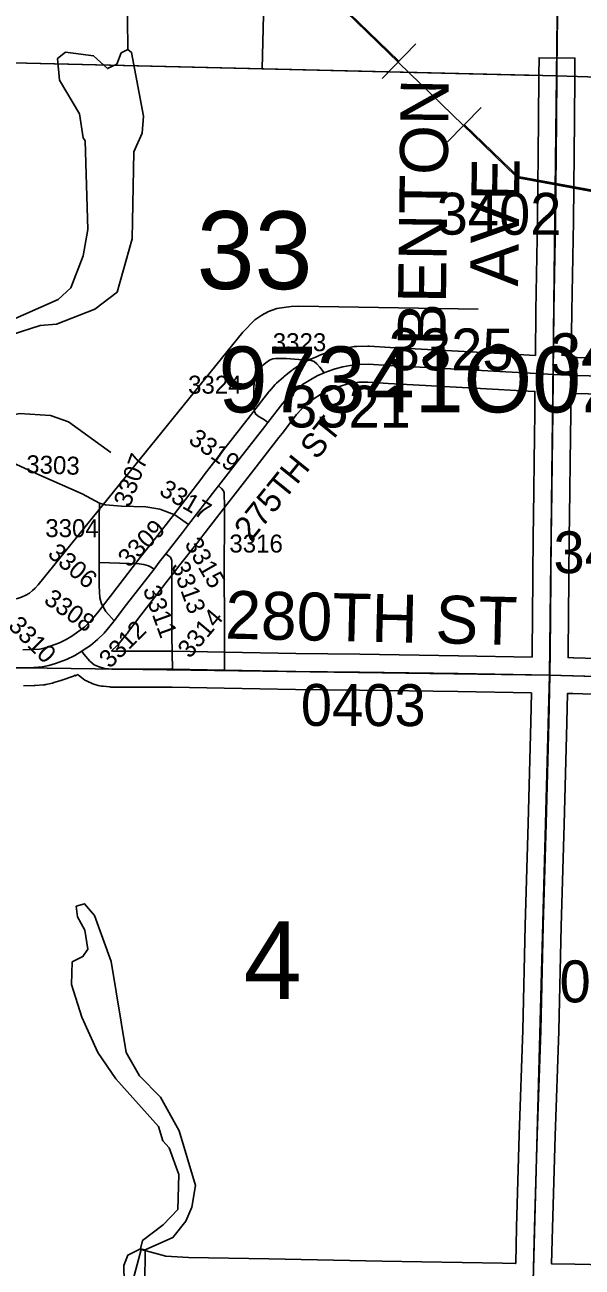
# Model space of a CAD drawing. Extents: x -157.2 to -99.3, y 12.2 to 46.2.
# Drawn here: x -144.748 to -143.818, y 22.152 to 24.227 of the extents above; entities that cross this region are included whole.
import ezdxf

# ---------------------------------------------------------------- set-up
doc = ezdxf.new("R2010")
doc.units = 0
for name, color, linetype in [('tdCoCityStreetMinor', 7, 'Continuous'), ('tdCoCorpBndry', 7, 'Continuous'), ('tdCoDirctArrow', 7, 'Continuous'), ('tdCoHydroRiver', 7, 'Continuous'), ('tdCoPipe', 7, 'Continuous'), ('tdCoSecRdNmbr', 7, 'Continuous'), ('tdCoSecRdTxt', 7, 'Continuous'), ('tdCoSecRteBand', 7, 'Continuous'), ('tdCoSecRteCL', 7, 'Continuous'), ('tdCoSectLine', 7, 'Continuous'), ('tdCoSectLinePart', 7, 'Continuous'), ('tdCoSectNmbr', 7, 'Continuous'), ('tdCoStrucPriMaintName', 7, 'Continuous'), ('tdCoSurfAsphaltUnbanded', 7, 'Continuous'), ('tdCoSurfConc', 7, 'Continuous'), ('tdCoSurfConcUnbanded', 7, 'Continuous'), ('tdCoSurfGravel', 7, 'Continuous'), ('tdCoSurfGravelUnbanded', 7, 'Continuous'), ('tdCoTwpBndryShd', 7, 'Continuous')]:
    doc.layers.add(name, color=color, linetype=linetype)

msp = doc.modelspace()

# ---------------------------------------------------------------- linework, layer by layer
at = {"layer": 'tdCoCityStreetMinor'}
msp.add_lwpolyline([(-143.8604, 24.1421), (-143.8598, 24.2064), (-143.8588, 24.2562), (-143.8573, 24.3977), (-143.8563, 24.434), (-143.8558, 24.5183)], dxfattribs=at)
at = {"layer": 'tdCoCorpBndry'}
msp.add_lwpolyline([(-143.7635, 24.3875), (-143.6972, 24.1343), (-143.6054, 23.7984), (-143.6103, 23.7579), (-143.6243, 23.7211), (-143.68, 23.6375), (-143.8278, 23.6417), (-143.8666, 23.6435), (-143.8652, 23.7494), (-143.8627, 23.9001), (-143.861, 24.0683), (-143.8604, 24.1421), (-144.3519, 24.154), (-144.3395, 24.6706)], dxfattribs=at)
at = {"layer": 'tdCoDirctArrow'}
msp.add_lwpolyline([(-143.9919, 23.7526), (-144.2911, 23.7574), (-144.3037, 23.757), (-144.3159, 23.7553), (-144.3274, 23.7536), (-144.3413, 23.7486), (-144.3527, 23.7422), (-144.3641, 23.7346), (-144.3846, 23.7142), (-144.7261, 23.2922), (-144.7306, 23.2864), (-144.7353, 23.2823), (-144.7402, 23.2783), (-144.7462, 23.2747), (-144.7537, 23.2712), (-144.7601, 23.2691), (-144.7684, 23.2674), (-144.7835, 23.2674), (-145.0438, 23.274)], dxfattribs=at)
at = {"layer": 'tdCoHydroRiver'}
for points in [[(-145.0194, 24.7742), (-144.9128, 24.7502), (-144.8286, 24.7205), (-144.6998, 24.6515), (-144.6677, 24.6189), (-144.6375, 24.5784), (-144.6293, 24.5386), (-144.6196, 24.4988), (-144.6146, 24.4592), (-144.6072, 24.4447), (-144.5973, 24.3591), (-144.5858, 24.3255), (-144.5849, 24.3066), (-144.5776, 24.2889), (-144.5762, 24.1862)], [(-145.0435, 23.7042), (-144.9954, 23.679), (-144.9227, 23.6813), (-144.875, 23.6923), (-144.8197, 23.6937), (-144.7223, 23.7252), (-144.6954, 23.7274), (-144.6315, 23.7522), (-144.5942, 23.7809), (-144.5692, 23.8701), (-144.566, 24.0153), (-144.5524, 24.0465), (-144.5499, 24.0748), (-144.57, 24.1813), (-144.5762, 24.1862)], [(-144.6475, 24.0338), (-144.6505, 24.0387), (-144.6571, 24.0784), (-144.69, 24.1347), (-144.6935, 24.1712), (-144.6805, 24.1818), (-144.6334, 24.1755), (-144.6104, 24.1542), (-144.5944, 24.1616), (-144.5874, 24.1803), (-144.5762, 24.1862)], [(-145.0435, 23.7042), (-145.0352, 23.7166), (-145.0174, 23.7302), (-144.9857, 23.7323), (-144.8443, 23.7134), (-144.779, 23.7302), (-144.6925, 23.7684), (-144.6713, 23.7882), (-144.6507, 23.8413), (-144.6429, 23.8852), (-144.6475, 24.0338)], [(-144.8558, 23.5559), (-144.7572, 23.5779), (-144.7052, 23.5746), (-144.6755, 23.5641), (-144.6046, 23.5128)], [(-144.6626, 22.7551), (-144.6601, 22.7376), (-144.6482, 22.7151), (-144.6429, 22.6833), (-144.6512, 22.671), (-144.6689, 22.6621), (-144.6701, 22.6242), (-144.6529, 22.57), (-144.6265, 22.5107), (-144.5963, 22.467), (-144.5248, 22.3872), (-144.5177, 22.3633), (-144.507, 22.3519), (-144.4911, 22.3072), (-144.493, 22.2488), (-144.5175, 22.2228), (-144.5515, 22.197), (-144.5552, 22.1829)], [(-144.6626, 22.7551), (-144.6483, 22.7593), (-144.6316, 22.7398), (-144.6041, 22.6631), (-144.5791, 22.5107), (-144.5567, 22.472), (-144.5216, 22.4361), (-144.4903, 22.3798), (-144.4633, 22.2889), (-144.4692, 22.2527), (-144.4794, 22.2294), (-144.5009, 22.2017), (-144.5473, 22.1811)], [(-144.5552, 22.1829), (-144.576, 22.1726), (-144.5829, 22.1554), (-144.5816, 22.1001), (-144.5574, 22.0661), (-144.5266, 22.0446), (-144.5134, 22.0126), (-144.5071, 22.0108)], [(-144.5552, 22.1829), (-144.5473, 22.1811)], [(-144.5473, 22.1811), (-144.5476, 22.1243), (-144.5449, 22.1115), (-144.4932, 22.0498)]]:
    msp.add_lwpolyline(points, dxfattribs=at)
at = {"layer": 'tdCoPipe'}
for p, q in [((-144.0958, 24.1953), (-144.1518, 24.1375)), ((-143.9866, 24.0894), (-144.0427, 24.0316))]:
    msp.add_line(p, q, dxfattribs=at)
for points in [[(-143.1022, 23.5122), (-143.2095, 23.8428), (-143.9285, 23.9743), (-144.6565, 24.6805), (-145.5794, 24.8267), (-145.6123, 26.3736), (-146.0293, 26.3674), (-146.0413, 27.397)], [(-144.1238, 24.1664), (-144.3399, 24.376)], [(-143.7528, 23.9399), (-143.9223, 23.9709), (-144.0147, 24.0605)]]:
    msp.add_lwpolyline(points, dxfattribs=at)
at = {"layer": 'tdCoSecRteBand'}
for points in [[(-144.7517, 23.1832), (-144.7349, 23.1837), (-144.7238, 23.1846), (-144.7156, 23.1864), (-144.7061, 23.1893), (-144.6902, 23.195), (-144.679, 23.2005), (-144.6698, 23.206), (-144.6478, 23.222), (-144.647, 23.2227), (-144.6378, 23.2317), (-144.6244, 23.248), (-144.6229, 23.25), (-144.6021, 23.2774), (-144.6021, 23.2775), (-144.602, 23.2776), (-144.5563, 23.3368), (-144.5475, 23.3482), (-144.5474, 23.3483), (-144.5473, 23.3483), (-144.5364, 23.3623), (-144.5085, 23.3979), (-144.4985, 23.4108), (-144.4546, 23.4678), (-144.4545, 23.4679), (-144.4545, 23.4679), (-144.4486, 23.4755), (-144.4137, 23.5207), (-144.4136, 23.5207), (-144.4136, 23.5207), (-144.3716, 23.5747), (-144.3663, 23.5815), (-144.3415, 23.6138), (-144.3408, 23.6146), (-144.3401, 23.6154), (-144.3304, 23.6263), (-144.3292, 23.6276), (-144.3279, 23.6288), (-144.3165, 23.639), (-144.316, 23.6394), (-144.3155, 23.6399), (-144.3036, 23.6496), (-144.3022, 23.6507), (-144.3008, 23.6516), (-144.2845, 23.6621), (-144.2833, 23.6628), (-144.282, 23.6635), (-144.273, 23.6681), (-144.272, 23.6687), (-144.2709, 23.6691), (-144.2604, 23.6735), (-144.2546, 23.6759), (-144.2537, 23.6763), (-144.2528, 23.6766), (-144.2402, 23.681), (-144.2394, 23.6813), (-144.2385, 23.6815), (-144.2256, 23.6851), (-144.2239, 23.6856), (-144.2222, 23.6859), (-144.2101, 23.6878), (-144.1986, 23.6898), (-144.1963, 23.6901), (-144.194, 23.6902), (-144.1758, 23.6904), (-144.1747, 23.6904), (-144.1737, 23.6904), (-144.1385, 23.6884), (-144.1384, 23.6884), (-144.1384, 23.6884), (-144.0968, 23.686), (-143.9945, 23.6804), (-143.8962, 23.6751), (-143.8952, 23.7498), (-143.8952, 23.7498), (-143.8952, 23.7499), (-143.8927, 23.9005), (-143.891, 24.0686), (-143.8904, 24.1424), (-143.8901, 24.1724), (-143.8301, 24.1718), (-143.8304, 24.1419), (-143.831, 24.068), (-143.831, 24.068), (-143.831, 24.068), (-143.8327, 23.8998), (-143.8327, 23.8997), (-143.8327, 23.8996), (-143.8352, 23.749), (-143.8363, 23.6721), (-143.8353, 23.6721), (-143.8266, 23.6717), (-143.6791, 23.6675)], [(-143.9016, 23.1714), (-143.9016, 23.1715), (-143.9014, 23.1829), (-143.9009, 23.2377), (-143.9009, 23.2377), (-143.9009, 23.2377), (-143.8996, 23.3731), (-143.8994, 23.4061), (-143.8994, 23.4062), (-143.8994, 23.4063), (-143.8977, 23.5409), (-143.8977, 23.5409), (-143.8977, 23.5409), (-143.8972, 23.5773), (-143.8969, 23.6139), (-143.897, 23.6139), (-143.897, 23.6149), (-143.898, 23.615), (-143.898, 23.6151), (-143.9977, 23.6205), (-143.9977, 23.6205), (-143.9977, 23.6205), (-144.1001, 23.6261), (-144.1002, 23.6261), (-144.1003, 23.6261), (-144.1418, 23.6285), (-144.176, 23.6304), (-144.1909, 23.6302), (-144.2004, 23.6286), (-144.2005, 23.6286), (-144.2006, 23.6286), (-144.211, 23.6269), (-144.2214, 23.624), (-144.2323, 23.6202), (-144.2372, 23.6182), (-144.2466, 23.6142), (-144.2533, 23.6108), (-144.267, 23.602), (-144.277, 23.5938), (-144.2867, 23.5852), (-144.2946, 23.5763), (-144.3188, 23.5449), (-144.3241, 23.538), (-144.3241, 23.5379), (-144.3242, 23.5379), (-144.3662, 23.4839), (-144.4012, 23.4388), (-144.4071, 23.4312), (-144.451, 23.3742), (-144.461, 23.3611), (-144.4611, 23.361), (-144.4612, 23.3609), (-144.4892, 23.3253), (-144.5001, 23.3114), (-144.5088, 23.3001), (-144.5544, 23.2411), (-144.575, 23.2138), (-144.5769, 23.2113), (-144.5773, 23.2108), (-144.5777, 23.2103), (-144.5925, 23.1923), (-144.5936, 23.191), (-144.5947, 23.1899), (-144.6033, 23.1815), (-144.6012, 23.1813), (-144.5091, 23.181), (-144.5088, 23.181), (-144.5086, 23.181), (-144.5011, 23.1809), (-144.4142, 23.1793), (-144.2957, 23.1771), (-144.1893, 23.1761), (-144.1892, 23.1761), (-144.1891, 23.1761), (-144.0244, 23.1736), (-144.0243, 23.1736), (-144.0243, 23.1736), (-143.9016, 23.1714), (-143.9016, 23.1714)], [(-143.6808, 23.6075), (-143.8286, 23.6117), (-143.8289, 23.6117), (-143.8292, 23.6117), (-143.8369, 23.6121), (-143.8372, 23.5768), (-143.8372, 23.5767), (-143.8372, 23.5766), (-143.8377, 23.5401), (-143.8394, 23.4056), (-143.8396, 23.3726), (-143.8396, 23.3726), (-143.8396, 23.3726), (-143.8409, 23.2372), (-143.8414, 23.1822), (-143.8414, 23.182), (-143.8414, 23.1819), (-143.8416, 23.1704), (-143.8324, 23.1702), (-143.8322, 23.1702), (-143.832, 23.1702), (-143.7166, 23.1665)], [(-144.5695, 22.1236), (-144.5542, 22.1816), (-144.5252, 22.174), (-144.5131, 22.1708), (-144.475, 22.1685), (-144.3412, 22.1661), (-144.152, 22.1626), (-144.152, 22.1626), (-144.152, 22.1626), (-144.0854, 22.1614), (-143.9511, 22.1589), (-143.9293, 22.1587), (-143.929, 22.1587), (-143.9275, 22.2189), (-143.9275, 22.219), (-143.9275, 22.2191), (-143.9231, 22.3735), (-143.9231, 22.3735), (-143.9231, 22.3736), (-143.9171, 22.5483), (-143.9132, 22.7232), (-143.9132, 22.7233), (-143.9132, 22.7234), (-143.9083, 22.8935), (-143.9036, 23.063), (-143.9027, 23.1114), (-144.0253, 23.1137), (-144.1899, 23.1161), (-144.2964, 23.1171), (-144.2965, 23.1171), (-144.2966, 23.1171), (-144.4153, 23.1193), (-144.5022, 23.1209), (-144.5095, 23.121), (-144.6029, 23.1213), (-144.6045, 23.1213), (-144.606, 23.1215), (-144.6172, 23.1226), (-144.62, 23.1229), (-144.623, 23.1232), (-144.6258, 23.1241), (-144.633, 23.1263), (-144.6344, 23.1268), (-144.6358, 23.1274), (-144.6439, 23.1308), (-144.6478, 23.1325), (-144.651, 23.1351), (-144.6587, 23.1413), (-144.6597, 23.1421), (-144.6634, 23.1398), (-144.6641, 23.141), (-144.6652, 23.1404), (-144.6667, 23.1397), (-144.6683, 23.1391), (-144.6865, 23.1325), (-144.6873, 23.1322), (-144.6881, 23.132), (-144.6996, 23.1286), (-144.7006, 23.1283), (-144.7017, 23.128), (-144.7129, 23.1256), (-144.7148, 23.1252), (-144.7167, 23.125), (-144.7306, 23.1238), (-144.7315, 23.1237), (-144.7324, 23.1237), (-144.7506, 23.1232)], [(-143.7185, 23.1065), (-143.8337, 23.1102), (-143.8427, 23.1104), (-143.8436, 23.0618), (-143.8436, 23.0617), (-143.8436, 23.0615), (-143.8483, 22.8919), (-143.8483, 22.8918), (-143.8483, 22.8918), (-143.8532, 22.7218), (-143.8572, 22.5468), (-143.8572, 22.5466), (-143.8572, 22.5464), (-143.8631, 22.3717), (-143.8675, 22.2174), (-143.869, 22.1579), (-143.8304, 22.1575), (-143.8302, 22.1574), (-143.8301, 22.1574), (-143.6493, 22.1533)]]:
    msp.add_lwpolyline(points, dxfattribs=at)
at = {"layer": 'tdCoSecRteCL'}
msp.add_line((-144.5017, 23.1509), (-144.4148, 23.1493), dxfattribs=at)
for points in [[(-143.8666, 23.6435), (-143.8652, 23.7494), (-143.8627, 23.9001), (-143.861, 24.0683), (-143.8604, 24.1421)], [(-144.3425, 23.5632), (-144.3484, 23.5676), (-144.3588, 23.5735), (-144.363, 23.5775), (-144.3652, 23.5824), (-144.3659, 23.6224), (-144.3644, 23.6379), (-144.362, 23.6455), (-144.3578, 23.6522), (-144.3523, 23.6576), (-144.3493, 23.6601), (-144.3457, 23.663), (-144.34, 23.667), (-144.3343, 23.6697), (-144.3297, 23.6702), (-144.3117, 23.6702), (-144.2776, 23.6672), (-144.2702, 23.6665), (-144.2653, 23.6648), (-144.2609, 23.6611), (-144.2559, 23.6557), (-144.2488, 23.6458)], [(-144.2488, 23.6458), (-144.243, 23.6483), (-144.2304, 23.6526), (-144.2175, 23.6563), (-144.2053, 23.6582), (-144.1936, 23.6602), (-144.1754, 23.6604), (-144.1401, 23.6585), (-144.0985, 23.656), (-143.9961, 23.6504), (-143.8842, 23.6444), (-143.8666, 23.6435)], [(-144.3425, 23.5632), (-144.3177, 23.5955), (-144.308, 23.6064), (-144.2965, 23.6166), (-144.2846, 23.6264), (-144.2683, 23.6368), (-144.2593, 23.6414), (-144.2488, 23.6458)], [(-143.8721, 23.1409), (-143.8714, 23.1825), (-143.8709, 23.2374), (-143.8696, 23.3728), (-143.8694, 23.4059), (-143.8677, 23.5405), (-143.8672, 23.577), (-143.8666, 23.6435)], [(-143.8666, 23.6435), (-143.8278, 23.6417), (-143.68, 23.6375), (-143.6538, 23.6367), (-143.642, 23.6364), (-143.6038, 23.6353), (-143.534, 23.6332), (-143.5201, 23.6328), (-143.4703, 23.6314), (-143.4516, 23.6307), (-143.4134, 23.6293), (-143.3862, 23.6283), (-143.3676, 23.6276)], [(-144.4249, 23.4571), (-144.3899, 23.5023), (-144.3478, 23.5563), (-144.3425, 23.5632)], [(-144.8682, 23.4761), (-144.8529, 23.4899), (-144.8439, 23.4986), (-144.8365, 23.5051), (-144.8278, 23.5087), (-144.8159, 23.5109), (-144.7995, 23.5089), (-144.7876, 23.5046), (-144.7233, 23.4749), (-144.6526, 23.4442), (-144.6236, 23.4282)], [(-144.4748, 23.3925), (-144.4308, 23.4495), (-144.4249, 23.4571)], [(-144.4148, 23.1493), (-144.415, 23.246), (-144.4155, 23.2965), (-144.4148, 23.4223), (-144.4153, 23.4455), (-144.4167, 23.4487), (-144.4199, 23.4529), (-144.4249, 23.4571)], [(-144.6239, 23.3291), (-144.6239, 23.4033), (-144.6236, 23.4282)], [(-144.6236, 23.4282), (-144.6137, 23.4254), (-144.5867, 23.4235), (-144.5462, 23.4221), (-144.5228, 23.4186), (-144.4977, 23.4088), (-144.4748, 23.3925)], [(-144.5128, 23.3438), (-144.4848, 23.3795), (-144.4748, 23.3925)], [(-144.5325, 23.3184), (-144.5237, 23.3298), (-144.5128, 23.3438)], [(-144.5017, 23.1509), (-144.5026, 23.2063), (-144.5026, 23.3133), (-144.5028, 23.3328), (-144.5048, 23.338), (-144.5085, 23.3402), (-144.5128, 23.3438)], [(-144.5989, 23.2319), (-144.613, 23.2477), (-144.6202, 23.26), (-144.6229, 23.2704), (-144.6239, 23.2901), (-144.6239, 23.3291)], [(-144.6239, 23.3291), (-144.6069, 23.3288), (-144.5576, 23.3271), (-144.5494, 23.3259), (-144.542, 23.3239), (-144.5383, 23.3222), (-144.5325, 23.3184)], [(-144.5989, 23.2319), (-144.5782, 23.2593), (-144.5325, 23.3184)], [(-144.6532, 23.181), (-144.6505, 23.1827), (-144.6383, 23.1909), (-144.6269, 23.2004), (-144.6157, 23.2114), (-144.6008, 23.2294), (-144.5989, 23.2319)], [(-144.6532, 23.181), (-144.6646, 23.1741), (-144.6784, 23.1673), (-144.6967, 23.1608), (-144.7081, 23.1574), (-144.7193, 23.1549), (-144.7332, 23.1537), (-144.7514, 23.1532)], [(-144.6532, 23.181), (-144.6497, 23.1762), (-144.6398, 23.1646), (-144.6322, 23.1584), (-144.6241, 23.155), (-144.6169, 23.1528), (-144.6141, 23.1525), (-144.6029, 23.1513), (-144.5091, 23.151), (-144.5017, 23.1509)], [(-144.4148, 23.1493), (-144.2961, 23.1471), (-144.1895, 23.1461), (-144.0248, 23.1436), (-143.8721, 23.1409)], [(-143.8997, 22.1283), (-143.8975, 22.2182), (-143.8931, 22.3726), (-143.8872, 22.5474), (-143.8832, 22.7225), (-143.8783, 22.8927), (-143.8736, 23.0624), (-143.8721, 23.1409)], [(-143.8721, 23.1409), (-143.8329, 23.1402), (-143.7175, 23.1365), (-143.5846, 23.1321), (-143.4186, 23.1276), (-143.3526, 23.1271)]]:
    msp.add_lwpolyline(points, dxfattribs=at)
at = {"layer": 'tdCoSectLine'}
for points in [[(-143.8607, 24.1421), (-143.8497, 25.1417)], [(-144.8616, 24.1662), (-143.8607, 24.1421)], [(-143.8725, 23.1409), (-143.8607, 24.1421)], [(-143.8607, 24.1421), (-142.8668, 24.1102)], [(-144.8712, 23.155), (-143.8725, 23.1409)], [(-143.9001, 22.1283), (-143.8725, 23.1409)], [(-143.8725, 23.1409), (-142.8769, 23.1119)]]:
    msp.add_lwpolyline(points, dxfattribs=at)
at = {"layer": 'tdCoSectLinePart'}
msp.add_lwpolyline([(-144.8616, 24.1662), (-143.8908, 24.1428)], dxfattribs=at)
at = {"layer": 'tdCoSurfAsphaltUnbanded'}
msp.add_lwpolyline([(-144.8682, 23.4761), (-144.8529, 23.4899), (-144.8439, 23.4986), (-144.8365, 23.5051), (-144.8278, 23.5087), (-144.8159, 23.5109), (-144.7995, 23.5089), (-144.7876, 23.5046), (-144.7233, 23.4749), (-144.6526, 23.4442), (-144.6236, 23.4282)], dxfattribs=at)
at = {"layer": 'tdCoSurfConc'}
for points in [[(-143.8666, 23.6435), (-143.8652, 23.7494), (-143.8627, 23.9001), (-143.861, 24.0683), (-143.8604, 24.1421)], [(-144.6532, 23.181), (-144.6505, 23.1827), (-144.6383, 23.1909), (-144.6269, 23.2004), (-144.6157, 23.2114), (-144.6008, 23.2294), (-144.5989, 23.2319), (-144.5782, 23.2593), (-144.5325, 23.3184), (-144.5237, 23.3298), (-144.5128, 23.3438), (-144.4848, 23.3795), (-144.4748, 23.3925), (-144.4308, 23.4495), (-144.4249, 23.4571), (-144.3899, 23.5023), (-144.3478, 23.5563), (-144.3425, 23.5632), (-144.3177, 23.5955), (-144.308, 23.6064), (-144.2965, 23.6166), (-144.2846, 23.6264), (-144.2683, 23.6368), (-144.2593, 23.6414), (-144.2488, 23.6458), (-144.243, 23.6483), (-144.2304, 23.6526), (-144.2175, 23.6563), (-144.2053, 23.6582), (-144.1936, 23.6602), (-144.1754, 23.6604), (-144.1401, 23.6585), (-144.0985, 23.656), (-143.9961, 23.6504), (-143.8842, 23.6444), (-143.8666, 23.6435)], [(-143.8666, 23.6435), (-143.8278, 23.6417), (-143.68, 23.6375)], [(-145.733, 23.1924), (-145.7084, 23.1904), (-145.6712, 23.1892), (-145.551, 23.1844), (-145.4481, 23.1795), (-145.3939, 23.1773), (-145.2805, 23.1724), (-145.1603, 23.1671), (-145.0365, 23.162), (-144.9623, 23.1588), (-144.8796, 23.1552), (-144.7847, 23.1535), (-144.7514, 23.1532), (-144.7332, 23.1537), (-144.7193, 23.1549), (-144.7081, 23.1574), (-144.6967, 23.1608), (-144.6784, 23.1673), (-144.6646, 23.1741), (-144.6532, 23.181), (-144.6532, 23.181)]]:
    msp.add_lwpolyline(points, dxfattribs=at)
at = {"layer": 'tdCoSurfConcUnbanded'}
for points in [[(-144.4148, 23.1493), (-144.415, 23.246), (-144.4155, 23.2965), (-144.4148, 23.4223), (-144.4153, 23.4455), (-144.4167, 23.4487), (-144.4199, 23.4529), (-144.4249, 23.4571)], [(-144.6236, 23.4282), (-144.6137, 23.4254), (-144.5867, 23.4235), (-144.5462, 23.4221), (-144.5228, 23.4186), (-144.4977, 23.4088), (-144.4748, 23.3925)], [(-144.5017, 23.1509), (-144.5026, 23.2063), (-144.5026, 23.3133), (-144.5028, 23.3328), (-144.5048, 23.338), (-144.5085, 23.3402), (-144.5128, 23.3438)], [(-144.6239, 23.3291), (-144.6069, 23.3288), (-144.5576, 23.3271), (-144.5494, 23.3259), (-144.542, 23.3239), (-144.5383, 23.3222), (-144.5325, 23.3184)]]:
    msp.add_lwpolyline(points, dxfattribs=at)
at = {"layer": 'tdCoSurfGravel'}
for points in [[(-143.8721, 23.1409), (-143.8714, 23.1825), (-143.8709, 23.2374), (-143.8696, 23.3728), (-143.8694, 23.4059), (-143.8677, 23.5405), (-143.8672, 23.577), (-143.8666, 23.6435)], [(-144.6532, 23.181), (-144.6497, 23.1762), (-144.6398, 23.1646), (-144.6322, 23.1584), (-144.6241, 23.155), (-144.6169, 23.1528), (-144.6141, 23.1525)], [(-144.6141, 23.1525), (-144.6029, 23.1513), (-144.5091, 23.151), (-144.5017, 23.1509), (-144.4148, 23.1493), (-144.2961, 23.1471), (-144.1895, 23.1461), (-144.0248, 23.1436), (-143.8721, 23.1409), (-143.8329, 23.1402), (-143.7175, 23.1365), (-143.5846, 23.1321), (-143.4186, 23.1276), (-143.3526, 23.1271)], [(-143.9194, 21.1235), (-143.918, 21.1921), (-143.917, 21.2382), (-143.9143, 21.3778), (-143.9096, 21.4229), (-143.9042, 21.4836), (-143.9029, 21.5233), (-143.9029, 21.544), (-143.9032, 21.5832), (-143.9049, 21.6103), (-143.9074, 21.6352), (-143.9074, 21.7087), (-143.9044, 21.871), (-143.9017, 22.0446), (-143.8997, 22.1283), (-143.8975, 22.2182), (-143.8931, 22.3726), (-143.8872, 22.5474), (-143.8832, 22.7225), (-143.8783, 22.8927), (-143.8736, 23.0624), (-143.8721, 23.1409)]]:
    msp.add_lwpolyline(points, dxfattribs=at)
at = {"layer": 'tdCoSurfGravelUnbanded'}
for points in [[(-144.3425, 23.5632), (-144.3484, 23.5676), (-144.3588, 23.5735), (-144.363, 23.5775), (-144.3652, 23.5824), (-144.3659, 23.6224), (-144.3644, 23.6379), (-144.362, 23.6455), (-144.3578, 23.6522), (-144.3523, 23.6576), (-144.3493, 23.6601)], [(-144.2488, 23.6458), (-144.2559, 23.6557), (-144.2609, 23.6611), (-144.2653, 23.6648), (-144.2702, 23.6665), (-144.2776, 23.6672), (-144.3117, 23.6702), (-144.3297, 23.6702), (-144.3343, 23.6697), (-144.34, 23.667), (-144.3457, 23.663), (-144.3493, 23.6601)], [(-144.5989, 23.2319), (-144.613, 23.2477), (-144.6202, 23.26), (-144.6229, 23.2704), (-144.6239, 23.2901), (-144.6239, 23.3291), (-144.6239, 23.4033), (-144.6236, 23.4282)]]:
    msp.add_lwpolyline(points, dxfattribs=at)
at = {"layer": 'tdCoTwpBndryShd'}
msp.add_lwpolyline([(-146.8729, 23.2324), (-145.8715, 23.197), (-144.8712, 23.155), (-143.8725, 23.1409), (-142.8769, 23.1119), (-141.8842, 23.0634), (-140.8917, 23.0263), (-139.9101, 22.9943), (-138.9141, 22.9595), (-137.92, 22.9236), (-137.2834, 22.8964), (-136.9243, 22.8946), (-135.9317, 22.8553), (-134.9318, 22.8156), (-134.4557, 22.7924)], dxfattribs=at)

# ---------------------------------------------------------------- texts
at = {"layer": 'tdCoSecRdNmbr'}
for s, height, rotation, p in [('3402', 0.07, 359.8902, (-144.061, 23.8769)), ('3325', 0.07, 359.89, (-144.1409, 23.6504)), ('3323', 0.03, 359.8897, (-144.3344, 23.6823)), ('3403', 0.07, 359.8902, (-143.8721, 23.6422)), ('3324', 0.03, 359.8897, (-144.4757, 23.6113)), ('3321', 0.07, 359.8899, (-144.3122, 23.5549)), ('3319', 0.03, 324.8896, (-144.4768, 23.5304)), ('3303', 0.03, 358.0274, (-144.7462, 23.4787)), ('3307', 0.03, 69.8905, (-144.5728, 23.4202)), ('3317', 0.03, 329.8895, (-144.5258, 23.4436)), ('3304', 0.03, 359.8895, (-144.714, 23.3717)), ('3309', 0.03, 44.8903, (-144.5747, 23.3195)), ('3315', 0.03, 299.8899, (-144.4823, 23.3606)), ('3316', 0.03, 359.8897, (-144.4068, 23.346)), ('3404', 0.07, 359.8902, (-143.866, 23.3114)), ('3306', 0.03, 319.8895, (-144.7118, 23.3412)), ('3313', 0.03, 289.8901, (-144.504, 23.3248)), ('3308', 0.03, 324.8894, (-144.7182, 23.2628)), ('3311', 0.03, 289.8901, (-144.5515, 23.2846)), ('3310', 0.03, 314.8895, (-144.7774, 23.2218)), ('3314', 0.03, 49.8905, (-144.4728, 23.1676)), ('3312', 0.03, 44.8903, (-144.6063, 23.151)), ('0403', 0.07, 359.8899, (-144.2876, 23.0564)), ('0302', 0.07, 359.8902, (-143.8559, 22.5947))]:
    msp.add_text(s, height=height, rotation=rotation, dxfattribs=at).set_placement(p)
at = {"layer": 'tdCoSecRdTxt'}
for s, height, rotation, p in [('BENTON', 0.08, 89.2576, (-144.0463, 23.6908)), ('AVE', 0.08, 89.2576, (-143.925, 23.79)), ('275TH ST', 0.04, 51.0596, (-144.3711, 23.3628)), ('280TH ST', 0.08, 358.7385, (-144.4143, 23.2022))]:
    msp.add_text(s, height=height, rotation=rotation, dxfattribs=at).set_placement(p)
at = {"layer": 'tdCoSectNmbr'}
for s, rotation, p in [('33', 359.8899, (-144.4615, 23.7861)), ('4', 359.8897, (-144.3829, 22.6003))]:
    msp.add_text(s, height=0.13, rotation=rotation, dxfattribs=at).set_placement(p)
at = {"layer": 'tdCoStrucPriMaintName'}
msp.add_text('97341O029', height=0.11, dxfattribs=at).set_placement((-144.425, 23.58))

doc.saveas('drawing.dxf')
